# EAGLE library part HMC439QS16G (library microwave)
HBT DIGITAL PHASE-FREQUENCY DETECTOR, 10 - 1300 MHz Source: http://www.hittite.com/product_info/product_specs/dividersdetectors/hmc439qs16g.pdf
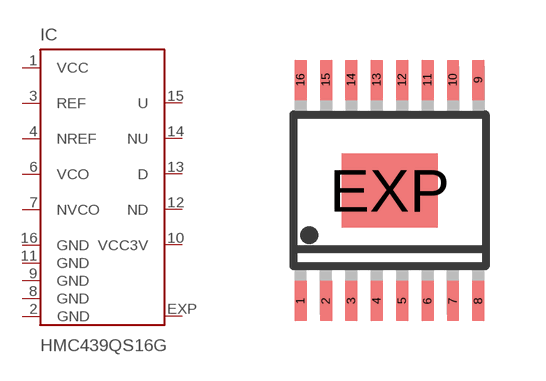
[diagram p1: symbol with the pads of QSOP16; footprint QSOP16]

Designator prefix IC

## HMC439QS16G  [QSOP16]
1  VCC  pwr
2  GND  pwr
3  REF  in
4  NREF  in
6  VCO  in
7  NVCO  in
8  GND  pwr
9  GND  pwr
10  VCC3V  pas
11  GND  pwr
12  ND  oc
13  D  oc
14  NU  oc
15  U  oc
16  GND  pwr
EXP  EXP  pas

## Footprint QSOP16 (pad centres in mm)
QSOP 16 Source: http://www.hittite.com/product_info/product_specs/dividersdetectors/hmc439qs16g.pdf
smd 0.3 x 1: 1 -2.223,-2.768; 2 -1.587,-2.768; 3 -0.953,-2.768; 4 -0.318,-2.768; 5 0.318,-2.768; 6 0.953,-2.768; 7 1.587,-2.768; 8 2.223,-2.768; 9 2.223,2.768; 10 1.587,2.768; 11 0.953,2.768; 12 0.318,2.768; 13 -0.318,2.768; 14 -0.953,2.768; 15 -1.587,2.768; 16 -2.223,2.768
smd 2.4 x 1.85: EXP 0,0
